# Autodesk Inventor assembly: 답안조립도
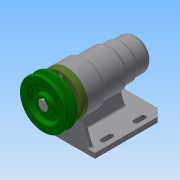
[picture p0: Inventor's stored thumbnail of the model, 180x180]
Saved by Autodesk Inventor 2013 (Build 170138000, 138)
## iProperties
Created: 2017-09
Part Number: 답안조립도
Document SubType Name: Assembly
Designer: Administrator
Author: Administrator
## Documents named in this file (11)
- C:\Users\Administrator\Desktop\470908V1013\답안조립도.iam
- C:\Users\Administrator\Desktop\470908V1013\답안도면.ipt
- C:\Users\Administrator\Desktop\470908V1013\베어링 51202.ipt
- C:\Users\Administrator\Desktop\470908V1013\축.ipt
- C:\Users\Administrator\Desktop\470908V1013\어댑터슬리브.ipt
- C:\Users\Administrator\Desktop\470908V1013\볼트 M4 x 12.ipt
- C:\Users\Administrator\Desktop\470908V1013\베어링 6004.ipt
- C:\Users\Administrator\Desktop\470908V1013\커버.ipt
- C:\Users\Administrator\Desktop\470908V1013\V벨트풀리.ipt
- C:\Users\Administrator\Desktop\470908V1013\키 5 x 5 x 16.ipt
- C:\Users\Administrator\Desktop\470908V1013\멈춤나사 M3x8.ipt
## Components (1 placed, 1 different names)
1. V벨트풀리:1 — 각도:3
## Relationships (1: Angle 1)
- 각도:3 [Angle]: V벨트풀리:1
